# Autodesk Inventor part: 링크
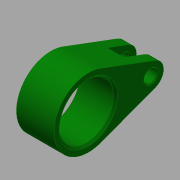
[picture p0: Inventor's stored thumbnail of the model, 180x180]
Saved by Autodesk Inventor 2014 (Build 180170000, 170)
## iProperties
Created: 2016-08
Part Number: 링크
Material: 강철, 탄소
Document SubType Name: Modeling
Designer: mduedu
Density: 7.87 g/cm^3
Appearance: Dark Green
Author: mduedu
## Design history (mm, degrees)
sketch "스케치1"
  geometry: L1 (32.1, 5.62)-(5.775, 15.456); L2 (32.1, -5.62)-(5.775, -15.456); C1 r 13 at (0, 0); C2 r 3 at (30, 0); A1 r 16.5 centre (0, 0) between (5.775, 15.456) and (5.775, -15.456); A2 r 6 centre (30, 0) between (32.1, 5.62) and (32.1, -5.62); 1 further point
  constraints: 4 centre point, 4 end point, 4 point on circle, 4 tangent, 3 coincident, 1 horizontal alignment
  dimensions: "d0" = 33 diameter of A1; "d2" = 12 diameter of A2; "d3" = 30 distance of A2.centre point (0, 0); "d4" = 26 diameter of C1; "d5" = 6 diameter of C2
extrude "돌출1" new body sketch "스케치1" stored distance "d6" = 18; taper "d7" = 0 deg
sketch "스케치2"
  geometry: L1 (-9, 36)-(9, 36) reference; L2 (0, 0)-(0, 36); L3 (-4, 36)-(4, 36); L4 (4, 36)-(4, 22); L5 (4, 22)-(-4, 22); L6 (-4, 22)-(-4, 36)
  constraints: 10 end point, 2 midpoint, 2 parallel, 1 horizontal, 1 perpendicular, 1 point on line
  dimensions: "d8" = 8 distance between parallel lines of L4 L6; "d10" = 14 distance of L3.end L4.end
extrude "돌출2" cut sketch "스케치2" stored distance "d11" = 20; taper "d12" = 0 deg
chamfer "모따기1" distance "d13" = 1; stored, may be unused: second distance "d14" = 2, angle "d15" = 45 deg
chamfer "모따기2" distance "d16" = 0.5; stored, may be unused: second distance "d17" = 2, angle "d18" = 45 deg
node "솔리드1"
